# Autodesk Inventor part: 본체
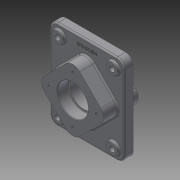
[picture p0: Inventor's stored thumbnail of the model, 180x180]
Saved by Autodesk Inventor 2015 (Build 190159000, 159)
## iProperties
Created: 2026-07
Part Number: 본체
Material: 일반
Document SubType Name: Modeling
Designer: user
Density: 1 g/cm^3
Appearance: 기본값
Author: user
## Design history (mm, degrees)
sketch "스케치1"
  geometry: L1 (-60, 90)-(60, 90); L2 (75, 75)-(75, -75); L3 (60, -90)-(-60, -90); L4 (-75, -75)-(-75, 75); L5 (-75, 90)-(75, -90); L6 (75, 90)-(-75, -90); A1 r 15 centre (60, 75) between (75, 75) and (60, 90); A2 r 15 centre (-60, 75) between (-60, 90) and (-75, 75); A3 r 15 centre (-60, -75) between (-75, -75) and (-60, -90); A4 r 15 centre (60, -75) between (60, -90) and (75, -75); 1 further point
  constraints: 12 end point, 8 point on circle, 8 point on line, 8 tangent, 4 centre point, 3 equal radius, 2 midpoint, 2 parallel, 1 horizontal, 1 perpendicular
  dimensions: "d0" = 150 distance of L5.end L6.end; "d1" = 180 distance of L6.start L5.end; "d2" = 15 radius of A1
extrude "돌출1" new body sketch "스케치1" stored distance "d3" = 18; taper "d4" = 0 deg
sketch "스케치2"
  geometry: L1 (-75, -75)-(-75, 75) reference; L2 (-60, 90)-(60, 90) reference; L3 (75, 75)-(75, -75) reference; L4 (60, -90)-(-60, -90) reference; C1 r 11 at (-55, 70); A1 r 15 centre (-60, -75) between (-75, -75) and (-60, -90) reference; A2 r 15 centre (-60, 75) between (-60, 90) and (-75, 75) reference; A3 r 15 centre (60, 75) between (75, 75) and (60, 90) reference; A4 r 15 centre (60, -75) between (60, -90) and (75, -75) reference; 1 further point
  constraints: 1 centre point
  dimensions: "d5" = 22 diameter of C1; "d6" = 20 distance from line of C1.centre L1; "d7" = 20 distance from line of L2 C1.centre
extrude "돌출2" join sketch "스케치2" distance "d8" = 5; taper "d9" = 0 deg
hole "구멍1" diameter "d12" = 11; stored, may be unused: countersink angle "d16" = 90 deg, drill point angle "d18" = 118 deg; dims "d10" = 10, "d11" = 10, "d13" = 6, "d14" = 4, "d15" = 2, "d17" = 8
sketch "스케치3"
  geometry: L1 (-75, -75)-(-75, 75) reference; L2 (-60, 90)-(60, 90) reference; L3 (75, 75)-(75, -75) reference; L4 (60, -90)-(-60, -90) reference; L5 (-14.142, 56.569)-(-56.569, 14.142); L6 (-56.569, -14.142)-(-14.142, -56.569); L7 (14.142, -56.569)-(56.569, -14.142); L8 (56.569, 14.142)-(14.142, 56.569); C1 r 5.5 at (55, -70) reference; C2 r 5.5 at (55, 70) reference; C3 r 5.5 at (-55, -70) reference; C4 r 11 at (55, -70) reference; C5 r 11 at (55, 70) reference; C6 r 11 at (-55, -70) reference; C7 r 5.5 at (-55, 70) reference; C8 r 11 at (-55, 70) reference; A1 r 15 centre (-60, -75) between (-75, -75) and (-60, -90) reference; A2 r 15 centre (-60, 75) between (-60, 90) and (-75, 75) reference; A3 r 15 centre (60, 75) between (75, 75) and (60, 90) reference; A4 r 15 centre (60, -75) between (60, -90) and (75, -75) reference; A5 r 20 centre (0, 42.426) between (14.142, 56.569) and (-14.142, 56.569); A6 r 20 centre (42.426, 0) between (56.569, -14.142) and (56.569, 14.142); A7 r 20 centre (-42.426, 0) between (-56.569, 14.142) and (-56.569, -14.142); A8 r 20 centre (0, -42.426) between (-14.142, -56.569) and (14.142, -56.569); 5 further points
  constraints: 8 end point, 8 point on circle, 8 point on line, 8 tangent, 4 centre point, 3 equal radius, 3 vertical alignment, 2 horizontal alignment, 2 parallel, 1 perpendicular
  dimensions: "d26" = 100 distance of point (0, 70.711) point (-70.711, 0); "d27" = 20 radius of A5
extrude "돌출3" join sketch "스케치3" distance "d28" = 29; taper "d30" = 0 deg; dims "d29" = 41, "d31" = 0
sketch "스케치4"
  geometry: L1 (-14.142, -56.569)-(-56.569, -14.142) reference; L2 (-56.569, 14.142)-(-14.142, 56.569) reference; L3 (14.142, 56.569)-(56.569, 14.142) reference; L4 (56.569, -14.142)-(14.142, -56.569) reference; C1 r 31 at (0, 0); A1 r 20 centre (-42.426, 0) between (-56.569, 14.142) and (-56.569, -14.142) reference; A2 r 20 centre (0, 42.426) between (14.142, 56.569) and (-14.142, 56.569) reference; A3 r 20 centre (42.426, 0) between (56.569, -14.142) and (56.569, 14.142) reference; A4 r 20 centre (0, -42.426) between (-14.142, -56.569) and (14.142, -56.569) reference; 1 further point
  constraints: 1 centre point, 1 coincident
  dimensions: "d32" = 62 diameter of C1
hole "구멍2" sketch "스케치4" at (0, 0) diameter "d33" = 54; stored, may be unused: countersink angle "d37" = 90 deg, drill point angle "d39" = 118 deg; dims "d34" = 6, "d35" = 62, "d36" = 22, "d38" = 8
hole "구멍3" diameter "d42" = 62; stored, may be unused: countersink angle "d46" = 90 deg, drill point angle "d48" = 0 deg; dims "d43" = 6, "d44" = 62, "d45" = 22, "d47" = 22, "d82" = 10, "d83" = 10
sketch "스케치5"
  geometry: L1 (0, 0)-(0, 48)
  constraints: 2 end point, 1 vertical
  dimensions: "d49" = 48 distance of L1.start L1.end
hole "구멍4" sketch "스케치5" at (0, 48) diameter "d50" = 4.917; stored, may be unused: countersink angle "d54" = 90 deg, drill point angle "d56" = 118 deg; dims "d51" = 10, "d52" = 62, "d53" = 22, "d55" = 13
sketch "스케치6"
  geometry: L1 (-14.142, -56.569)-(-56.569, -14.142) reference; L2 (-56.569, 14.142)-(-14.142, 56.569) reference; L3 (14.142, 56.569)-(56.569, 14.142) reference; L4 (56.569, -14.142)-(14.142, -56.569) reference; L5 (-75, -75)-(-75, 75) reference; L6 (-60, 90)-(60, 90) reference; L7 (75, 75)-(75, -75) reference; L8 (60, -90)-(-60, -90) reference; C1 r 27 at (0, 0) reference; C2 r 5.5 at (55, -70) reference; C3 r 5.5 at (55, 70) reference; C4 r 5.5 at (-55, -70) reference; C5 r 11 at (55, -70) reference; C6 r 11 at (55, 70) reference; C7 r 11 at (-55, -70) reference; C8 r 5.5 at (-55, 70) reference; C9 r 11 at (-55, 70) reference; A1 r 20 centre (-42.426, 0) between (-56.569, 14.142) and (-56.569, -14.142) reference; A2 r 20 centre (0, 42.426) between (14.142, 56.569) and (-14.142, 56.569) reference; A3 r 20 centre (42.426, 0) between (56.569, -14.142) and (56.569, 14.142) reference; A4 r 20 centre (0, -42.426) between (-14.142, -56.569) and (14.142, -56.569) reference; A5 r 15 centre (-60, -75) between (-75, -75) and (-60, -90) reference; A6 r 15 centre (-60, 75) between (-60, 90) and (-75, 75) reference; A7 r 15 centre (60, 75) between (75, 75) and (60, 90) reference; A8 r 15 centre (60, -75) between (60, -90) and (75, -75) reference; 2 further points
  constraints: 1 vertical alignment, 1 other
  dimensions: "d60" = 15 distance from line of L6 point (0, 75)
feature "엠보싱1" sketch "스케치6" dims "d0" = 150, "d1" = 180, "d2" = 15, "d8" = 5, "d61" = 0.5, "d62" = 0
chamfer "모따기1" distance "d64" = 1; stored, may be unused: second distance "d65" = 2, angle "d66" = 45 deg
fillet "모깎기2" dims "d67" = 3
fillet "모깎기3" dims "d68" = 3
fillet "모깎기4" dims "d69" = 3
sketch "스케치7"
  geometry: L1 (0, 0)-(0, -48)
  constraints: 2 end point, 1 vertical
  dimensions: "d70" = 48 distance of L1.start L1.end
hole "구멍5" sketch "스케치7" at (0, -48) diameter "d71" = 4.917; stored, may be unused: countersink angle "d75" = 90 deg, drill point angle "d77" = 118 deg; dims "d72" = 10, "d73" = 62, "d74" = 22, "d76" = 13
fillet "모깎기5" dims "d81" = 3
sketch "스케치8"
  geometry: 1 further point
fillet "모깎기6" dims "d84" = 1
node "솔리드1"
pattern_linear "직사각형 패턴1"
pattern_circular "원형 패턴1" dims angle "d58" = 360 deg
pattern_circular "원형 패턴2" dims angle "d79" = 360 deg
node "절단 모서리 투영1"
node "절단 모서리 투영2"
node "절단 모서리 투영3"
node "절단 모서리 투영4"
